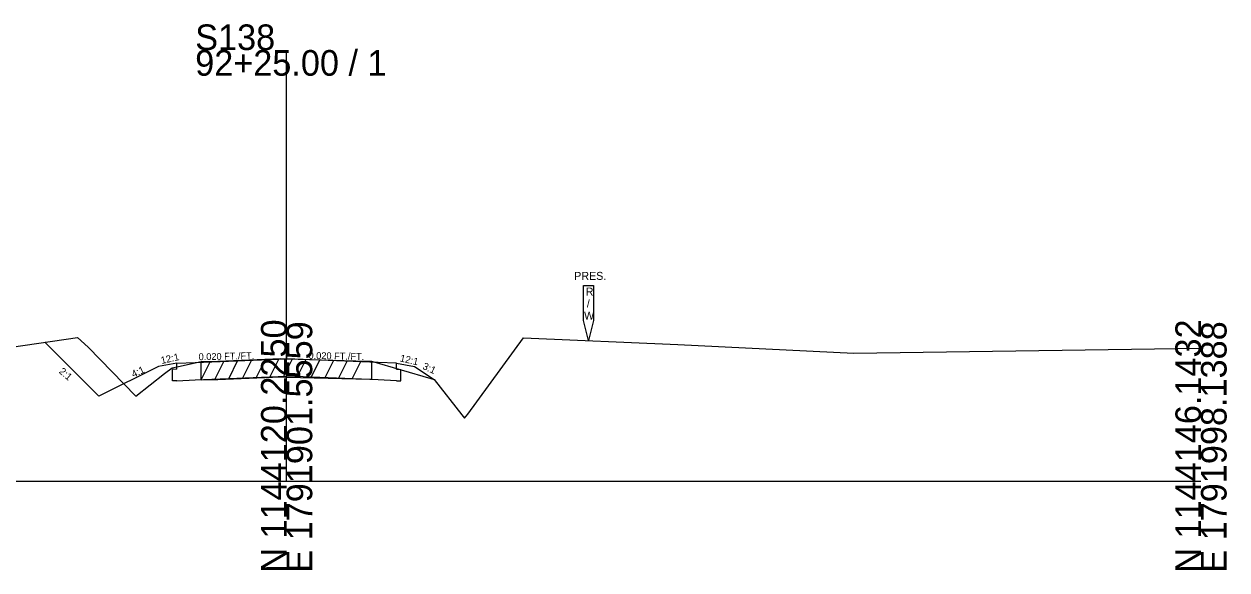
# Model space of a CAD drawing. Extents: x -26 to 1203, y -10 to 19606.
# Drawn here: x 1071.3 to 1202.8, y 4490.3 to 4550 of the extents above; entities that cross this region are included whole.
import ezdxf

# ---------------------------------------------------------------- set-up
doc = ezdxf.new("R2010")
doc.units = 0
for name, color, linetype in [('RD_EX_Driveway', 7, 'Continuous'), ('RD_GPK_XS_Cell', 7, 'Continuous'), ('RD_XS_Base', 7, 'Continuous'), ('RD_XS_EarthShd', 7, 'Continuous'), ('RD_XS_ExGround', 7, 'Continuous'), ('RD_XS_ExPaveRet', 7, 'Continuous'), ('RD_XS_ExRW', 7, 'Continuous'), ('RD_XS_Pave', 7, 'Continuous'), ('RD_XS_TX_Slope', 7, 'Continuous')]:
    doc.layers.add(name, color=color, linetype=linetype)

msp = doc.modelspace()

# ---------------------------------------------------------------- linework, layer by layer
at = {"layer": 'RD_GPK_XS_Cell'}
for p, q in [((1100, 4500), (1100, 4547.13)), ((1000, 4500), (1100, 4500)), ((1100, 4500), (1200, 4500))]:
    msp.add_line(p, q, dxfattribs=at)
at = {"layer": 'RD_XS_Base'}
for p, q in [((1088, 4512.25), (1088, 4512.89)), ((1112, 4512.25), (1112, 4512.89)), ((1088, 4512.25), (1087.5, 4512.23)), ((1087.5, 4510.96), (1087.5, 4512.23)), ((1090, 4511.07), (1100, 4511.48)), ((1110, 4511.07), (1100, 4511.48)), ((1112, 4512.25), (1112.5, 4512.23)), ((1112.5, 4510.96), (1112.5, 4512.23)), ((1088, 4510.98), (1087.5, 4510.96)), ((1088, 4510.98), (1090, 4511.07)), ((1112, 4510.98), (1110, 4511.07)), ((1112, 4510.98), (1112.5, 4510.96))]:
    msp.add_line(p, q, dxfattribs=at)
at = {"layer": 'RD_XS_EarthShd'}
for p, q in [((1079.47, 4509.29), (1073.57, 4515.2)), ((1086, 4512.56), (1079.47, 4509.29)), ((1088, 4512.89), (1086, 4512.56)), ((1112, 4512.89), (1114, 4512.56)), ((1114, 4512.56), (1116.13, 4511.11))]:
    msp.add_line(p, q, dxfattribs=at)
at = {"layer": 'RD_XS_ExGround'}
msp.add_lwpolyline([(1062.4, 4513.57), (1077.11, 4515.71), (1078.3, 4514.67), (1083.52, 4509.29), (1086.64, 4511.77), (1087.49, 4512.4), (1088.17, 4512.54), (1090.66, 4513.08), (1092.47, 4513.13), (1099.32, 4513.41), (1100, 4513.39), (1107.56, 4513.18), (1109.28, 4513.14), (1115.76, 4511.23), (1116.13, 4511.11), (1119.16, 4507.27), (1119.47, 4506.88), (1119.81, 4507.34), (1125.92, 4515.67), (1142.77, 4514.95), (1162.03, 4514), (1200, 4514.56)], dxfattribs=at)
at = {"layer": 'RD_XS_ExPaveRet'}
for p, q in [((1090.66, 4511.08), (1091.68, 4513.11)), ((1090.66, 4511.08), (1090.66, 4513.08)), ((1092.16, 4511.13), (1093.18, 4513.16)), ((1093.66, 4511.18), (1094.68, 4513.22)), ((1095.16, 4511.24), (1096.18, 4513.28)), ((1096.66, 4511.3), (1097.68, 4513.34)), ((1098.16, 4511.36), (1099.18, 4513.4)), ((1099.66, 4511.4), (1100.65, 4513.37)), ((1101.16, 4511.36), (1102.15, 4513.33)), ((1102.66, 4511.32), (1103.65, 4513.29)), ((1104.16, 4511.28), (1105.15, 4513.25)), ((1105.66, 4511.23), (1106.65, 4513.21)), ((1107.16, 4511.19), (1108.15, 4513.17)), ((1109.28, 4513.14), (1109.28, 4511.14)), ((1090.66, 4511.08), (1092.47, 4511.13)), ((1092.47, 4511.13), (1099.32, 4511.41)), ((1099.32, 4511.41), (1100, 4511.39)), ((1100, 4511.39), (1107.56, 4511.18)), ((1107.56, 4511.18), (1109.28, 4511.14))]:
    msp.add_line(p, q, dxfattribs=at)
at = {"layer": 'RD_XS_ExRW'}
msp.add_lwpolyline([(1132.45, 4521.39), (1133.55, 4521.39), (1133.55, 4517.56), (1133, 4515.37), (1132.45, 4517.56)], close=True, dxfattribs=at)
at = {"layer": 'RD_XS_Pave'}
for p, q in [((1088, 4512.89), (1090, 4512.97)), ((1090, 4512.97), (1100, 4513.39)), ((1110, 4512.97), (1100, 4513.39)), ((1112, 4512.89), (1110, 4512.97))]:
    msp.add_line(p, q, dxfattribs=at)

# ---------------------------------------------------------------- texts
at = {"layer": 'RD_EX_Driveway'}
msp.add_text('552.69', height=0.0975, rotation=90, dxfattribs=at).set_placement((1100.1, 4513.39))
at = {"layer": 'RD_GPK_XS_Cell'}
for s, p in [('S138', (1090, 4547.13)), ('92+25.00 / 1', (1090, 4544.33))]:
    msp.add_text(s, height=2.8, dxfattribs=at).set_placement(p)
for s, p in [('N 1144120.2250', (1100, 4490)), ('E 1791901.5559', (1102.8, 4490)), ('N 1144146.1432', (1200, 4490)), ('E 1791998.1388', (1202.8, 4490))]:
    msp.add_text(s, height=2.8, rotation=90, dxfattribs=at).set_placement(p)
at = {"layer": 'RD_XS_ExRW'}
for s, p in [('PRES.', (1131.45, 4522.01)), ('R', (1132.71, 4520.29)), ('/', (1132.83, 4518.98)), ('W', (1132.53, 4517.67))]:
    msp.add_text(s, height=0.875, dxfattribs=at).set_placement(p)
at = {"layer": 'RD_XS_TX_Slope'}
for s, height, rotation, p in [('12:1', 0.778, 12.7511, (1086.33, 4512.81)), ('0.020 FT./FT.', 0.7518, 1.1916, (1090.38, 4513.23)), ('0.020 FT./FT.', 0.7518, 358.8084, (1102.39, 4513.38)), ('12:1', 0.778, 347.2489, (1112.34, 4513.11)), ('4:1', 0.778, 24.919, (1083.24, 4511.31)), ('3:1', 0.778, 335.081, (1114.79, 4512.31)), ('2:1', 0.778, 319.3411, (1075.03, 4511.9))]:
    msp.add_text(s, height=height, rotation=rotation, dxfattribs=at).set_placement(p)

doc.saveas('drawing.dxf')
